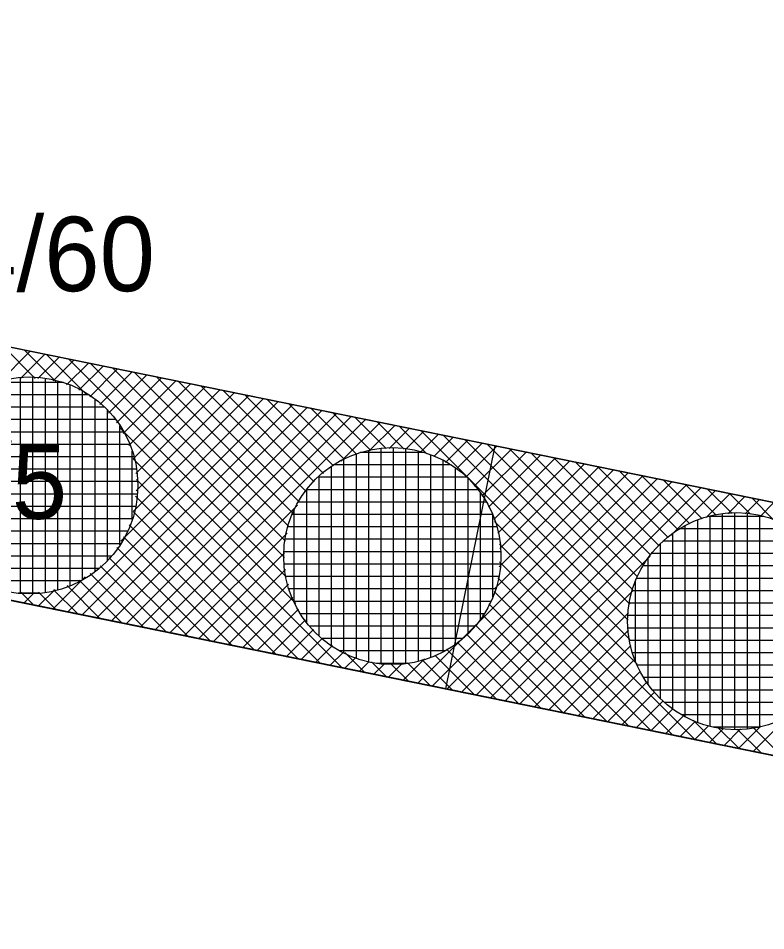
# Model space of a CAD drawing. Extents: x -566461 to -565198, y -1096301 to -1095707.
# Drawn here: x -565723.33 to -565711.28, y -1096140.23 to -1096125.52 of the extents above; entities that cross this region are included whole.
import ezdxf

# ---------------------------------------------------------------- set-up
doc = ezdxf.new("R2010")
doc.units = 0
for name, color, linetype in [('Vrstva 1', 7, 'Continuous'), ('Vrstva 40', 7, 'Continuous'), ('Vrstva 41', 7, 'Continuous'), ('Vrstva 42', 7, 'Continuous'), ('Vrstva 44', 7, 'Continuous')]:
    doc.layers.add(name, color=color, linetype=linetype)

msp = doc.modelspace()

# ---------------------------------------------------------------- linework, layer by layer
at = {"layer": 'Vrstva 1'}
for p, q in [((-565697.28, -1096140.23), (-565854, -1096108.33)), ((-565748.22, -1096125.78), (-565696.05, -1096136.4))]:
    msp.add_line(p, q, dxfattribs=at)
at = {"layer": 'Vrstva 41'}
for p, q in [((-565723.643, -1096131.394), (-565723.136, -1096130.887)), ((-565723.584, -1096130.796), (-565723.055, -1096131.325)), ((-565723.229, -1096130.868), (-565722.721, -1096131.377)), ((-565723.294, -1096131.327), (-565722.901, -1096130.935)), ((-565723.011, -1096131.327), (-565722.666, -1096130.982)), ((-565722.874, -1096130.94), (-565722.221, -1096131.593)), ((-565722.766, -1096131.365), (-565722.431, -1096131.03)), ((-565722.519, -1096131.012), (-565719.004, -1096134.528)), ((-565722.548, -1096131.43), (-565722.196, -1096131.078)), ((-565722.352, -1096131.517), (-565721.961, -1096131.126)), ((-565722.175, -1096131.623), (-565721.726, -1096131.174)), ((-565722.164, -1096131.085), (-565719.037, -1096134.212)), ((-565722.015, -1096131.745), (-565721.491, -1096131.222)), ((-565721.809, -1096131.157), (-565719.019, -1096133.947)), ((-565721.871, -1096131.885), (-565721.256, -1096131.269)), ((-565721.745, -1096132.041), (-565721.021, -1096131.317)), ((-565721.636, -1096132.215), (-565720.786, -1096131.365)), ((-565721.454, -1096131.229), (-565718.969, -1096133.714)), ((-565721.099, -1096131.302), (-565718.896, -1096133.504)), ((-565721.546, -1096132.408), (-565720.551, -1096131.413)), ((-565721.476, -1096132.621), (-565720.316, -1096131.461)), ((-565721.431, -1096132.858), (-565720.081, -1096131.509)), ((-565720.743, -1096131.374), (-565718.802, -1096133.316)), ((-565720.388, -1096131.446), (-565718.688, -1096133.147)), ((-565721.676, -1096133.952), (-565719.376, -1096131.652)), ((-565721.473, -1096133.466), (-565719.611, -1096131.604)), ((-565721.429, -1096133.14), (-565719.846, -1096131.556)), ((-565720.033, -1096131.518), (-565718.558, -1096132.994)), ((-565719.678, -1096131.591), (-565718.411, -1096132.857)), ((-565719.323, -1096131.663), (-565718.249, -1096132.737)), ((-565722.531, -1096135.09), (-565719.141, -1096131.7)), ((-565722.296, -1096135.138), (-565718.906, -1096131.748)), ((-565722.061, -1096135.186), (-565718.671, -1096131.796)), ((-565718.968, -1096131.735), (-565718.069, -1096132.634)), ((-565718.613, -1096131.808), (-565717.87, -1096132.55)), ((-565721.826, -1096135.234), (-565718.436, -1096131.843)), ((-565721.591, -1096135.281), (-565718.201, -1096131.891)), ((-565721.356, -1096135.329), (-565717.966, -1096131.939)), ((-565718.258, -1096131.88), (-565717.649, -1096132.488)), ((-565717.902, -1096131.952), (-565717.397, -1096132.457)), ((-565721.121, -1096135.377), (-565717.731, -1096131.987)), ((-565718.122, -1096132.661), (-565717.496, -1096132.035)), ((-565717.671, -1096132.493), (-565717.261, -1096132.083)), ((-565717.547, -1096132.024), (-565717.108, -1096132.464)), ((-565717.192, -1096132.097), (-565716.745, -1096132.544)), ((-565721.693, -1096132.121), (-565718.857, -1096134.957)), ((-565717.35, -1096132.455), (-565717.026, -1096132.13)), ((-565717.081, -1096132.468), (-565716.791, -1096132.178)), ((-565716.845, -1096132.515), (-565716.556, -1096132.226)), ((-565716.837, -1096132.169), (-565713.473, -1096135.533)), ((-565716.482, -1096132.241), (-565713.499, -1096135.224)), ((-565716.634, -1096132.587), (-565716.321, -1096132.274)), ((-565716.443, -1096132.679), (-565716.086, -1096132.322)), ((-565716.271, -1096132.79), (-565715.851, -1096132.37)), ((-565716.127, -1096132.314), (-565713.476, -1096134.964)), ((-565715.772, -1096132.386), (-565713.424, -1096134.734)), ((-565716.117, -1096132.919), (-565715.616, -1096132.417)), ((-565715.979, -1096133.064), (-565715.381, -1096132.465)), ((-565715.858, -1096133.225), (-565715.146, -1096132.513)), ((-565715.417, -1096132.458), (-565713.348, -1096134.527)), ((-565715.061, -1096132.53), (-565713.249, -1096134.343)), ((-565721.477, -1096132.621), (-565718.106, -1096135.991)), ((-565715.753, -1096133.403), (-565714.911, -1096132.561)), ((-565715.667, -1096133.6), (-565714.676, -1096132.609)), ((-565715.603, -1096133.819), (-565714.441, -1096132.657)), ((-565714.706, -1096132.603), (-565713.134, -1096134.175)), ((-565714.351, -1096132.675), (-565713.002, -1096134.025)), ((-565715.641, -1096134.706), (-565713.736, -1096132.8)), ((-565715.58, -1096134.361), (-565713.971, -1096132.752)), ((-565715.569, -1096134.067), (-565714.206, -1096132.704)), ((-565713.996, -1096132.747), (-565712.854, -1096133.89)), ((-565713.641, -1096132.819), (-565712.689, -1096133.771)), ((-565721.425, -1096132.955), (-565718.461, -1096135.919)), ((-565716.891, -1096136.238), (-565713.501, -1096132.848)), ((-565716.656, -1096136.286), (-565713.266, -1096132.896)), ((-565716.421, -1096136.334), (-565713.031, -1096132.944)), ((-565713.286, -1096132.892), (-565712.507, -1096133.67)), ((-565712.931, -1096132.964), (-565712.306, -1096133.588)), ((-565716.186, -1096136.382), (-565712.796, -1096132.991)), ((-565715.951, -1096136.43), (-565712.561, -1096133.039)), ((-565715.716, -1096136.477), (-565712.326, -1096133.087)), ((-565712.576, -1096133.036), (-565712.081, -1096133.531)), ((-565712.22, -1096133.109), (-565711.826, -1096133.503)), ((-565721.438, -1096133.224), (-565718.817, -1096135.846)), ((-565712.809, -1096133.853), (-565712.091, -1096133.135)), ((-565712.243, -1096133.57), (-565711.856, -1096133.183)), ((-565711.897, -1096133.507), (-565711.621, -1096133.231)), ((-565711.865, -1096133.181), (-565711.529, -1096133.517)), ((-565711.615, -1096133.507), (-565711.386, -1096133.279)), ((-565711.51, -1096133.253), (-565711.151, -1096133.612)), ((-565720.886, -1096135.425), (-565718.829, -1096133.368)), ((-565711.37, -1096133.545), (-565711.151, -1096133.326)), ((-565721.474, -1096133.471), (-565719.172, -1096135.774)), ((-565721.543, -1096133.685), (-565719.527, -1096135.702)), ((-565715.654, -1096133.635), (-565713.356, -1096135.933)), ((-565720.651, -1096135.473), (-565718.997, -1096133.819)), ((-565721.633, -1096133.878), (-565719.882, -1096135.629)), ((-565715.574, -1096133.998), (-565712.424, -1096137.147)), ((-565721.741, -1096134.053), (-565720.237, -1096135.557)), ((-565720.416, -1096135.521), (-565719.035, -1096134.14)), ((-565721.867, -1096134.211), (-565720.592, -1096135.485)), ((-565715.572, -1096134.283), (-565712.779, -1096137.075)), ((-565715.481, -1096136.525), (-565713.147, -1096134.191)), ((-565722.01, -1096134.35), (-565720.947, -1096135.413)), ((-565720.181, -1096135.569), (-565719.022, -1096134.409)), ((-565722.766, -1096135.042), (-565722.248, -1096134.524)), ((-565722.346, -1096134.58), (-565721.658, -1096135.268)), ((-565722.169, -1096134.473), (-565721.302, -1096135.34)), ((-565715.599, -1096134.539), (-565713.135, -1096137.003)), ((-565723.001, -1096134.994), (-565722.734, -1096134.727)), ((-565722.758, -1096134.733), (-565722.368, -1096135.123)), ((-565722.541, -1096134.667), (-565722.013, -1096135.196)), ((-565719.946, -1096135.616), (-565718.975, -1096134.645)), ((-565723.284, -1096134.773), (-565723.078, -1096134.979)), ((-565723.236, -1096134.947), (-565723.065, -1096134.776)), ((-565723.002, -1096134.773), (-565722.723, -1096135.051)), ((-565719.711, -1096135.664), (-565718.903, -1096134.856)), ((-565715.66, -1096134.76), (-565713.49, -1096136.931)), ((-565715.246, -1096136.573), (-565713.43, -1096134.757)), ((-565715.744, -1096134.959), (-565713.845, -1096136.858)), ((-565719.476, -1096135.712), (-565718.811, -1096135.047)), ((-565715.847, -1096135.139), (-565714.2, -1096136.786)), ((-565715.011, -1096136.621), (-565713.493, -1096135.103)), ((-565719.241, -1096135.76), (-565718.7, -1096135.219)), ((-565715.967, -1096135.301), (-565714.555, -1096136.714)), ((-565719.006, -1096135.808), (-565718.571, -1096135.373)), ((-565716.104, -1096135.448), (-565714.91, -1096136.641)), ((-565714.776, -1096136.669), (-565713.493, -1096135.385)), ((-565718.771, -1096135.856), (-565718.426, -1096135.511)), ((-565718.536, -1096135.903), (-565718.265, -1096135.632)), ((-565716.257, -1096135.578), (-565715.265, -1096136.569)), ((-565714.541, -1096136.717), (-565713.455, -1096135.63)), ((-565718.301, -1096135.951), (-565718.087, -1096135.737)), ((-565718.067, -1096135.747), (-565717.751, -1096136.063)), ((-565716.426, -1096135.692), (-565715.62, -1096136.497)), ((-565718.066, -1096135.999), (-565717.89, -1096135.823)), ((-565717.831, -1096136.047), (-565717.671, -1096135.887)), ((-565717.638, -1096135.894), (-565717.396, -1096136.135)), ((-565717.596, -1096136.095), (-565717.423, -1096135.921)), ((-565717.361, -1096136.143), (-565717.138, -1096135.919)), ((-565717.322, -1096135.927), (-565717.041, -1096136.208)), ((-565717.126, -1096136.19), (-565716.784, -1096135.849)), ((-565717.057, -1096135.909), (-565716.686, -1096136.28)), ((-565716.824, -1096135.859), (-565716.331, -1096136.352)), ((-565716.614, -1096135.786), (-565715.976, -1096136.425)), ((-565714.306, -1096136.764), (-565713.389, -1096135.847)), ((-565714.071, -1096136.812), (-565713.301, -1096136.043)), ((-565713.836, -1096136.86), (-565713.196, -1096136.22)), ((-565713.601, -1096136.908), (-565713.073, -1096136.38)), ((-565713.366, -1096136.956), (-565712.934, -1096136.523)), ((-565713.131, -1096137.004), (-565712.778, -1096136.651)), ((-565712.896, -1096137.051), (-565712.605, -1096136.76)), ((-565711.486, -1096137.338), (-565710.899, -1096136.752)), ((-565712.661, -1096137.099), (-565712.413, -1096136.851)), ((-565712.453, -1096136.836), (-565712.069, -1096137.22)), ((-565712.426, -1096137.147), (-565712.2, -1096136.921)), ((-565712.053, -1096136.953), (-565711.714, -1096137.292)), ((-565711.721, -1096137.291), (-565711.363, -1096136.933)), ((-565711.484, -1096136.956), (-565711.004, -1096137.437)), ((-565712.191, -1096137.195), (-565711.964, -1096136.968)), ((-565711.956, -1096137.243), (-565711.69, -1096136.977)), ((-565711.744, -1096136.979), (-565711.359, -1096137.364))]:
    msp.add_line(p, q, dxfattribs=at)
at = {"layer": 'Vrstva 42'}
msp.add_line((-565715.648, -1096132.411), (-565716.446, -1096136.329), dxfattribs=at)
msp.add_lwpolyline([(-565828.2, -1096027.12), (-565826.72, -1096023.51), (-565829.55, -1096025.32), (-565832.07, -1096026.09), (-565854, -1096108.33), (-565697.28, -1096140.23), (-565696.05, -1096136.4), (-565849.04, -1096105.26)], close=True, dxfattribs=at)
at = {"layer": 'Vrstva 44'}
for p, q in [((-565723.29, -1096134.792), (-565723.29, -1096131.306)), ((-565723.09, -1096134.797), (-565723.09, -1096131.302)), ((-565722.89, -1096134.78), (-565722.89, -1096131.321)), ((-565722.69, -1096134.738), (-565722.69, -1096131.363)), ((-565722.6, -1096131.39), (-565723.698, -1096131.39)), ((-565722.49, -1096134.669), (-565722.49, -1096131.43)), ((-565722.186, -1096131.59), (-565724.112, -1096131.59)), ((-565722.29, -1096134.572), (-565722.29, -1096131.528)), ((-565722.09, -1096134.442), (-565722.09, -1096131.66)), ((-565721.937, -1096131.79), (-565724.363, -1096131.79)), ((-565721.89, -1096134.262), (-565721.89, -1096131.838)), ((-565721.76, -1096131.99), (-565724.541, -1096131.99)), ((-565721.69, -1096134.011), (-565721.69, -1096132.087)), ((-565721.627, -1096132.19), (-565724.673, -1096132.19)), ((-565721.531, -1096132.39), (-565724.769, -1096132.39)), ((-565721.49, -1096133.598), (-565721.49, -1096132.498)), ((-565717.88, -1096135.839), (-565717.88, -1096132.541)), ((-565716.778, -1096132.52), (-565717.818, -1096132.52)), ((-565717.68, -1096135.898), (-565717.68, -1096132.484)), ((-565717.48, -1096135.929), (-565717.48, -1096132.451)), ((-565717.28, -1096135.938), (-565717.28, -1096132.44)), ((-565717.08, -1096135.924), (-565717.08, -1096132.455)), ((-565716.88, -1096135.888), (-565716.88, -1096132.493)), ((-565721.464, -1096132.59), (-565724.837, -1096132.59)), ((-565718.08, -1096135.755), (-565718.08, -1096132.624)), ((-565716.68, -1096135.826), (-565716.68, -1096132.555)), ((-565716.48, -1096135.734), (-565716.48, -1096132.644)), ((-565721.421, -1096132.79), (-565724.88, -1096132.79)), ((-565718.28, -1096135.638), (-565718.28, -1096132.742)), ((-565716.352, -1096132.72), (-565718.248, -1096132.72)), ((-565716.28, -1096135.61), (-565716.28, -1096132.77)), ((-565716.098, -1096132.92), (-565718.503, -1096132.92)), ((-565718.48, -1096135.48), (-565718.48, -1096132.899)), ((-565716.08, -1096135.442), (-565716.08, -1096132.936)), ((-565721.402, -1096132.99), (-565724.898, -1096132.99)), ((-565715.918, -1096133.12), (-565718.683, -1096133.12)), ((-565718.68, -1096135.263), (-565718.68, -1096133.117)), ((-565721.406, -1096133.19), (-565724.892, -1096133.19)), ((-565715.88, -1096135.211), (-565715.88, -1096133.17)), ((-565721.435, -1096133.39), (-565724.865, -1096133.39)), ((-565715.783, -1096133.32), (-565718.817, -1096133.32)), ((-565715.685, -1096133.52), (-565718.915, -1096133.52)), ((-565718.88, -1096134.939), (-565718.88, -1096133.439)), ((-565715.68, -1096134.847), (-565715.68, -1096133.532)), ((-565711.313, -1096133.55), (-565712.211, -1096133.55)), ((-565712.18, -1096136.938), (-565712.18, -1096133.543)), ((-565711.98, -1096136.976), (-565711.98, -1096133.506)), ((-565711.78, -1096136.989), (-565711.78, -1096133.492)), ((-565711.58, -1096136.979), (-565711.58, -1096133.5)), ((-565711.38, -1096136.946), (-565711.38, -1096133.533)), ((-565721.487, -1096133.59), (-565724.814, -1096133.59)), ((-565715.616, -1096133.72), (-565718.984, -1096133.72)), ((-565712.58, -1096136.785), (-565712.58, -1096133.696)), ((-565712.38, -1096136.875), (-565712.38, -1096133.604)), ((-565721.565, -1096133.79), (-565724.735, -1096133.79)), ((-565712.78, -1096136.66), (-565712.78, -1096133.82)), ((-565710.846, -1096133.75), (-565712.677, -1096133.75)), ((-565721.675, -1096133.99), (-565724.624, -1096133.99)), ((-565715.573, -1096133.92), (-565719.029, -1096133.92)), ((-565712.98, -1096136.494), (-565712.98, -1096133.987)), ((-565710.58, -1096133.95), (-565712.941, -1096133.95)), ((-565715.552, -1096134.12), (-565719.048, -1096134.12)), ((-565710.393, -1096134.15), (-565713.127, -1096134.15)), ((-565721.824, -1096134.19), (-565724.478, -1096134.19)), ((-565713.18, -1096136.262), (-565713.18, -1096134.218)), ((-565722.027, -1096134.39), (-565724.273, -1096134.39)), ((-565715.555, -1096134.32), (-565719.043, -1096134.32)), ((-565710.255, -1096134.35), (-565713.267, -1096134.35)), ((-565722.323, -1096134.59), (-565723.979, -1096134.59)), ((-565715.583, -1096134.52), (-565719.017, -1096134.52)), ((-565713.38, -1096135.897), (-565713.38, -1096134.583)), ((-565710.152, -1096134.55), (-565713.366, -1096134.55)), ((-565715.634, -1096134.72), (-565718.966, -1096134.72)), ((-565710.082, -1096134.75), (-565713.438, -1096134.75)), ((-565722.98, -1096134.79), (-565723.322, -1096134.79)), ((-565715.711, -1096134.92), (-565718.89, -1096134.92)), ((-565710.036, -1096134.95), (-565713.485, -1096134.95)), ((-565715.819, -1096135.12), (-565718.78, -1096135.12)), ((-565710.014, -1096135.15), (-565713.507, -1096135.15)), ((-565715.966, -1096135.32), (-565718.635, -1096135.32)), ((-565710.014, -1096135.35), (-565713.505, -1096135.35)), ((-565716.165, -1096135.52), (-565718.434, -1096135.52)), ((-565710.039, -1096135.55), (-565713.48, -1096135.55)), ((-565716.455, -1096135.72), (-565718.146, -1096135.72)), ((-565710.088, -1096135.75), (-565713.432, -1096135.75)), ((-565717.044, -1096135.92), (-565717.554, -1096135.92)), ((-565710.162, -1096135.95), (-565713.359, -1096135.95)), ((-565710.265, -1096136.15), (-565713.253, -1096136.15)), ((-565710.41, -1096136.35), (-565713.111, -1096136.35)), ((-565710.601, -1096136.55), (-565712.917, -1096136.55)), ((-565710.878, -1096136.75), (-565712.641, -1096136.75)), ((-565711.397, -1096136.95), (-565712.13, -1096136.95))]:
    msp.add_line(p, q, dxfattribs=at)
for centre in [(-565723.15, -1096133.05), (-565717.3, -1096134.19), (-565711.76, -1096135.24)]:
    msp.add_circle(centre, 1.75, dxfattribs=at)

# ---------------------------------------------------------------- texts
at = {"layer": 'Vrstva 40'}
for s, p in [('14/60', (-565725.14, -1096129.92)), ('9/5', (-565724.77, -1096133.59))]:
    msp.add_text(s, height=1.2, dxfattribs=at).set_placement(p)

doc.saveas('drawing.dxf')
